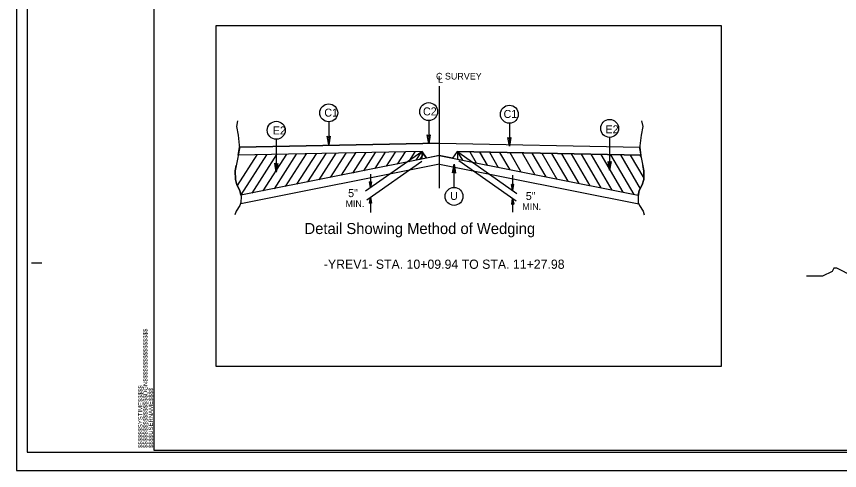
# Model space of a CAD drawing. Extents: x 1818040 to 1825768, y 638918 to 648046.
# Drawn here: x 1820431 to 1821432, y 644030 to 644582 of the extents above; entities that cross this region are included whole.
import ezdxf

# ---------------------------------------------------------------- set-up
doc = ezdxf.new("R2010")
doc.units = 0
for name, color, linetype in [('Old_Level_1', 7, 'Continuous'), ('Sheet Plot Border Inside CELL', 7, 'Continuous'), ('Sheet Plot Border Outside CELL', 7, 'Continuous'), ('Sheet Typical CELL', 7, 'Continuous'), ('Typical Detail Wedge2 CELL', 7, 'Continuous'), ('Typical ID Circle CELL', 7, 'Continuous'), ('Typical Slope Point Local CELL', 7, 'Continuous'), ('Typical Terminator CELL', 7, 'Continuous'), ('Typical Text Centerline CELL', 7, 'Continuous'), ('Typical Text General CELL', 7, 'Continuous'), ('Typical Text Grade Point CELL', 7, 'Continuous'), ('Typical Text ID Circle CELL', 7, 'Continuous')]:
    doc.layers.add(name, color=color, linetype=linetype)

msp = doc.modelspace()

# ---------------------------------------------------------------- linework, layer by layer
at = {"layer": 'Old_Level_1'}
msp.add_lwpolyline([(1820674, 644570.9), (1821287.9, 644570.9), (1821287.9, 644156.3), (1820674, 644156.3)], close=True, dxfattribs=at)
at = {"layer": 'Sheet Plot Border Inside CELL'}
msp.add_lwpolyline([(1822110.4, 645107.2), (1820443.9, 645107.2), (1820443.9, 644052.1), (1822110.4, 644052.1)], close=True, dxfattribs=at)
at = {"layer": 'Sheet Plot Border Outside CELL'}
msp.add_lwpolyline([(1822114.9, 645129.6), (1820430.9, 645129.6), (1820430.9, 644029.6), (1822114.9, 644029.6)], close=True, dxfattribs=at)
at = {"layer": 'Sheet Typical CELL'}
for p, q in [((1820430.9, 645129.6), (1820430.9, 644029.6)), ((1820449.4, 644282.1), (1820461.9, 644282.1)), ((1820597.9, 644054.6), (1820597.9, 644054.6)), ((1820597.9, 644054.6), (1820597.9, 644054.6)), ((1820597.9, 644054.6), (1820597.9, 644054.6)), ((1820597.9, 644054.6), (1820597.9, 644054.6)), ((1820597.9, 644054.6), (1820597.9, 644054.6)), ((1820597.9, 644054.6), (1820597.9, 644054.6)), ((1820430.9, 644029.6), (1822114.9, 644029.6))]:
    msp.add_line(p, q, dxfattribs=at)
msp.add_lwpolyline([(1822097.9, 645104.6), (1820597.9, 645104.6), (1820597.9, 644054.6), (1822097.9, 644054.6)], close=True, dxfattribs=at)
msp.add_lwpolyline([(1820635.4, 644054.6), (1820635.4, 644054.6)], dxfattribs=at)
at = {"layer": 'Typical Detail Wedge2 CELL'}
for p, q in [((1820945.5, 644372.9), (1820945.5, 644497)), ((1820699.8, 644455), (1820698.5, 644447.9)), ((1820945.5, 644372.9), (1820945.5, 644457.7)), ((1820698.5, 644447.9), (1820700.4, 644437.7)), ((1820700.4, 644437.7), (1820702.1, 644421.3)), ((1820945.5, 644427.7), (1820702, 644422.9)), ((1820702, 644422.9), (1820945.5, 644427.7)), ((1820945.5, 644427.7), (1821189, 644422.9)), ((1820945.5, 644427.7), (1821189, 644422.9)), ((1820702.1, 644421.3), (1820699.8, 644408.4)), ((1820700.6, 644413.1), (1820702, 644422.9)), ((1820924.2, 644417.6), (1820700.6, 644413.1)), ((1820924.2, 644417.6), (1820700.6, 644413.1)), ((1820795.3, 644415), (1820771.5, 644377.9)), ((1820807.3, 644415.2), (1820785.1, 644380.6)), ((1820819.3, 644415.5), (1820798.7, 644383.3)), ((1820831.4, 644415.7), (1820812.4, 644386.1)), ((1820843.4, 644415.9), (1820826, 644388.8)), ((1820855.4, 644416.2), (1820839.6, 644391.5)), ((1820867.4, 644416.4), (1820853.2, 644394.2)), ((1820923.9, 644417.4), (1820855.3, 644369.3)), ((1820879.5, 644416.7), (1820866.8, 644397)), ((1820891.5, 644416.9), (1820880.5, 644399.7)), ((1820903.5, 644417.2), (1820894.1, 644402.4)), ((1820915.6, 644417.4), (1820907.7, 644405.1)), ((1820917.2, 644407.2), (1820923.8, 644417.5)), ((1820925.9, 644415), (1820921.3, 644407.9)), ((1820923.8, 644417.5), (1820923.8, 644409)), ((1820929.6, 644409.5), (1820924.2, 644417.6)), ((1820924.2, 644417.3), (1820929.6, 644409.5)), ((1820967.1, 644417.6), (1820961.4, 644409.5)), ((1820967.1, 644417.6), (1820961.4, 644409.5)), ((1820966.7, 644417.4), (1820967, 644417.4)), ((1820967.1, 644417.6), (1821190.4, 644413.1)), ((1821190.4, 644413.1), (1820967.1, 644417.6)), ((1820973.8, 644407.2), (1820967.2, 644417.5)), ((1820967.2, 644417.5), (1820967.2, 644408.1)), ((1820968.9, 644416.3), (1821039.6, 644366.8)), ((1820982.3, 644417.3), (1820990.2, 644403.8)), ((1820994.2, 644417), (1821003.5, 644401.1)), ((1820994.4, 644416.7), (1821003.6, 644401.1)), ((1821006.2, 644416.8), (1821016.9, 644398.4)), ((1821018.6, 644416.5), (1821030.8, 644395.5)), ((1821030.8, 644416.3), (1821044.4, 644392.9)), ((1821046, 644416), (1821061.4, 644389.5)), ((1821057.9, 644415.7), (1821074.8, 644386.8)), ((1821069.9, 644415.5), (1821088.2, 644384.2)), ((1821081.8, 644415.3), (1821101.5, 644381.5)), ((1821093.8, 644415), (1821114.9, 644378.8)), ((1821189, 644422.9), (1821190.4, 644413.1)), ((1820699.8, 644408.4), (1820696.9, 644394.3)), ((1820723.1, 644413.5), (1820699.3, 644376.4)), ((1820735.1, 644413.8), (1820703.8, 644364.8)), ((1820945.9, 644412.8), (1820703.8, 644364.4)), ((1820747.1, 644414), (1820717, 644367)), ((1820759.2, 644414.3), (1820730.6, 644369.7)), ((1820771.2, 644414.5), (1820744.3, 644372.4)), ((1820783.2, 644414.7), (1820757.9, 644375.2)), ((1820924, 644405.6), (1820856.9, 644358.6)), ((1820945.2, 644412.8), (1820929.6, 644409.5)), ((1820945.2, 644412.8), (1821187.2, 644364.4)), ((1820961.4, 644409.5), (1820945.2, 644412.8)), ((1820968.8, 644406.6), (1821038.8, 644357.6)), ((1821105.7, 644414.8), (1821128.3, 644376.1)), ((1821117.7, 644414.6), (1821141.6, 644373.5)), ((1821129.6, 644414.3), (1821155, 644370.8)), ((1821141.6, 644414.1), (1821168.4, 644368.1)), ((1821153.5, 644413.8), (1821181.7, 644365.5)), ((1821165.5, 644413.6), (1821189.5, 644372.4)), ((1821177.4, 644413.4), (1821193.9, 644385.1)), ((1821189.3, 644413.1), (1821190.8, 644410.6)), ((1820945.4, 644402.4), (1820703.8, 644354)), ((1820945.6, 644402.4), (1821187.8, 644353.9)), ((1820696.9, 644394.3), (1820697.2, 644383.7)), ((1820846.6, 644392.9), (1820839, 644391.4)), ((1820861.5, 644390), (1820861.5, 644373.7)), ((1821034.4, 644389.1), (1821034.4, 644370.4)), ((1820697.2, 644383.7), (1820698.9, 644377)), ((1820698.9, 644377), (1820702.8, 644370.3)), ((1820861.5, 644373.7), (1820860.3, 644380.9)), ((1820861.5, 644379.9), (1820860.3, 644380.9)), ((1820861.5, 644373.7), (1820860.4, 644380.7)), ((1820860.6, 644380.6), (1820861.5, 644373.7)), ((1820861.5, 644373.7), (1820860.8, 644380.5)), ((1820861, 644380.3), (1820861.5, 644373.7)), ((1820861.5, 644373.7), (1820861.2, 644380.2)), ((1820861.3, 644380.1), (1820861.5, 644373.7)), ((1820861.5, 644373.7), (1820862.8, 644380.9)), ((1820862.8, 644380.9), (1820861.5, 644379.9)), ((1820862.6, 644380.7), (1820861.5, 644373.7)), ((1820861.5, 644373.7), (1820862.4, 644380.6)), ((1820862.2, 644380.5), (1820861.5, 644373.7)), ((1820861.5, 644373.7), (1820862.1, 644380.3)), ((1820861.9, 644380.2), (1820861.5, 644373.7)), ((1820861.5, 644373.7), (1820861.7, 644380.1)), ((1820861.5, 644379.9), (1820861.5, 644373.7)), ((1821034.4, 644370.4), (1821033.2, 644377.5)), ((1821034.4, 644376.6), (1821033.2, 644377.5)), ((1821034.4, 644370.4), (1821033.4, 644377.4)), ((1821033.5, 644377.3), (1821034.4, 644370.4)), ((1821034.4, 644370.4), (1821033.7, 644377.1)), ((1821033.9, 644377), (1821034.4, 644370.4)), ((1821034.4, 644370.4), (1821034.1, 644376.9)), ((1821034.2, 644376.8), (1821034.4, 644370.4)), ((1821034.4, 644370.4), (1821035.7, 644377.5)), ((1821035.7, 644377.5), (1821034.4, 644376.6)), ((1821035.5, 644377.4), (1821034.4, 644370.4)), ((1821034.4, 644370.4), (1821035.3, 644377.3)), ((1821035.2, 644377.1), (1821034.4, 644370.4)), ((1821034.4, 644370.4), (1821035, 644377)), ((1821034.8, 644376.9), (1821034.4, 644370.4)), ((1821034.4, 644370.4), (1821034.6, 644376.8)), ((1821034.4, 644376.6), (1821034.4, 644370.4)), ((1820702.8, 644370.3), (1820704.1, 644363)), ((1820703.9, 644355.7), (1820702.6, 644352.2)), ((1820704.1, 644363), (1820703.9, 644355.7)), ((1820861.5, 644361.9), (1820860.3, 644354.7)), ((1820860.3, 644354.7), (1820861.5, 644355.6)), ((1820860.4, 644354.8), (1820861.5, 644361.9)), ((1820861.5, 644361.9), (1820860.6, 644355)), ((1820860.8, 644355.1), (1820861.5, 644361.9)), ((1820861.5, 644361.9), (1820861, 644355.2)), ((1820861.2, 644355.4), (1820861.5, 644361.9)), ((1820861.5, 644361.9), (1820861.3, 644355.5)), ((1820861.5, 644361.9), (1820861.5, 644343.5)), ((1820861.5, 644361.9), (1820862.8, 644354.7)), ((1820861.5, 644355.6), (1820861.5, 644361.9)), ((1820861.7, 644355.5), (1820861.5, 644361.9)), ((1820861.5, 644361.9), (1820861.9, 644355.4)), ((1820862.1, 644355.2), (1820861.5, 644361.9)), ((1820861.5, 644361.9), (1820862.2, 644355.1)), ((1820862.4, 644355), (1820861.5, 644361.9)), ((1820861.5, 644361.9), (1820862.6, 644354.8)), ((1820861.5, 644355.6), (1820862.8, 644354.7)), ((1821034.4, 644360.7), (1821033.2, 644353.5)), ((1821033.4, 644353.7), (1821034.4, 644360.7)), ((1821034.4, 644360.7), (1821033.5, 644353.8)), ((1821033.7, 644354), (1821034.4, 644360.7)), ((1821034.4, 644360.7), (1821033.9, 644354.1)), ((1821034.1, 644354.2), (1821034.4, 644360.7)), ((1821034.4, 644360.7), (1821034.2, 644354.3)), ((1821034.4, 644360.7), (1821034.4, 644344)), ((1821034.4, 644360.7), (1821035.7, 644353.5)), ((1821034.4, 644354.5), (1821034.4, 644360.7)), ((1821034.6, 644354.3), (1821034.4, 644360.7)), ((1821034.4, 644360.7), (1821034.8, 644354.2)), ((1821035, 644354.1), (1821034.4, 644360.7)), ((1821034.4, 644360.7), (1821035.2, 644354)), ((1821035.3, 644353.8), (1821034.4, 644360.7)), ((1821034.4, 644360.7), (1821035.5, 644353.7)), ((1820698, 644345.3), (1820696.5, 644340.5)), ((1820702.6, 644352.2), (1820698, 644345.3)), ((1821033.2, 644353.5), (1821034.4, 644354.5)), ((1821034.4, 644354.5), (1821035.7, 644353.5))]:
    msp.add_line(p, q, dxfattribs=at)
for points in [[(1821191.3, 644455), (1821192.6, 644447.9), (1821190.6, 644437.7), (1821188.9, 644421.3), (1821191.3, 644408.4), (1821194.1, 644394.3), (1821193.9, 644383.7), (1821192.1, 644377), (1821188.3, 644370.3), (1821187, 644363), (1821187.2, 644355.7), (1821188.5, 644352.2), (1821193, 644345.3), (1821194.5, 644340.5)], [(1820703.8, 644364.4), (1820702.8, 644370.3), (1820698.9, 644377), (1820697.2, 644383.7), (1820696.9, 644394.3), (1820698.2, 644400.8)], [(1821187.2, 644364.4), (1821188.3, 644370.3), (1821192.1, 644377), (1821193.9, 644383.7), (1821194.1, 644394.3), (1821192.8, 644400.8)]]:
    msp.add_lwpolyline(points, dxfattribs=at)
at = {"layer": 'Typical ID Circle CELL'}
for p, q in [((1820932.3, 644455.3), (1820932.3, 644427.2)), ((1820810.7, 644453.8), (1820810.7, 644425.7)), ((1821030.4, 644452.2), (1821030.4, 644424.1)), ((1820746.9, 644432.7), (1820746.9, 644392.7)), ((1821152.4, 644434.9), (1821152.4, 644394.9)), ((1820963.1, 644374), (1820963.1, 644402.1))]:
    msp.add_line(p, q, dxfattribs=at)
for centre in [(1820810.7, 644464.7), (1820932.3, 644466.2), (1821030.4, 644463), (1821152.4, 644445.8), (1820746.9, 644443.5), (1820963.1, 644363.1)]:
    msp.add_circle(centre, 10.9, dxfattribs=at)
at = {"layer": 'Typical Slope Point Local CELL'}
msp.add_lwpolyline([(1821469.7, 644271.8), (1821454.2, 644269.9), (1821450.3, 644269.9), (1821444.4, 644269.9), (1821440.5, 644269.9), (1821436.7, 644271.8), (1821432.8, 644273.8), (1821428.9, 644275.7), (1821425, 644275.7), (1821423, 644271.8), (1821419.1, 644269.9), (1821415.2, 644267.9), (1821411.4, 644266), (1821407.5, 644266), (1821403.6, 644266), (1821399.7, 644266), (1821395.8, 644266), (1821391.9, 644266)], dxfattribs=at)
at = {"layer": 'Typical Terminator CELL'}
for points in [[(1820812.5, 644436.2), (1820810.7, 644425.7), (1820808.8, 644436.3), (1820810.7, 644434.9)], [(1820812.5, 644436.2), (1820810.7, 644425.7), (1820808.8, 644436.3), (1820810.7, 644434.9)], [(1820934.1, 644437.8), (1820932.3, 644427.2), (1820930.4, 644437.8), (1820932.3, 644436.5)], [(1820934.1, 644437.8), (1820932.3, 644427.2), (1820930.4, 644437.8), (1820932.3, 644436.5)], [(1821032.2, 644434.6), (1821030.4, 644424.1), (1821028.5, 644434.7), (1821030.4, 644433.3)], [(1821154.2, 644405.5), (1821152.4, 644394.9), (1821150.5, 644405.5), (1821152.4, 644404.2)], [(1820748.8, 644403.2), (1820746.9, 644392.7), (1820745.1, 644403.3), (1820746.9, 644402)], [(1820748.8, 644403.2), (1820746.9, 644392.7), (1820745.1, 644403.3), (1820746.9, 644402)], [(1820961.3, 644391.6), (1820963.1, 644402.1), (1820965, 644391.5), (1820963.1, 644392.9)], [(1820961.3, 644391.6), (1820963.1, 644402.1), (1820965, 644391.5), (1820963.1, 644392.9)]]:
    msp.add_lwpolyline(points, close=True, dxfattribs=at)

# ---------------------------------------------------------------- texts
at = {"layer": 'Sheet Typical CELL'}
for s, p in [('$$$$$$$$$$$$$$$$DGN$$$$$$$$$$$$$$$$', (1820590.3, 644057)), ('$$$$$$SYSTIME$$$$$', (1820584.2, 644057)), ('$$$$USERNAME$$$$', (1820596.9, 644057))]:
    msp.add_text(s, height=5.25, rotation=90, dxfattribs=at).set_placement(p)
at = {"layer": 'Typical Detail Wedge2 CELL'}
for s, height, p in [('5"', 9.73, (1820834.3, 644362.2)), ('5"', 9.73, (1821050.4, 644358.7)), ('MIN.', 8.13, (1820831.1, 644350.2)), ('MIN.', 8.13, (1821046.1, 644346.7))]:
    msp.add_text(s, height=height, dxfattribs=at).set_placement(p)
at = {"layer": 'Typical Text Centerline CELL'}
for s, p in [('C SURVEY ', (1820941.2, 644505.2)), ('L', (1820943.6, 644501.4))]:
    msp.add_text(s, height=8.13, dxfattribs=at).set_placement(p)
at = {"layer": 'Typical Text General CELL'}
msp.add_text('Detail Showing Method of Wedging', height=13.428, dxfattribs=at).set_placement((1820781.3, 644317.3))
at = {"layer": 'Typical Text Grade Point CELL'}
msp.add_text('-YREV1- STA. 10+09.94 TO STA. 11+27.98', height=11.19, dxfattribs=at).set_placement((1820804.8, 644275))
at = {"layer": 'Typical Text ID Circle CELL'}
for s, p in [('C1', (1820805.4, 644460.1)), ('C2', (1820925.4, 644461.6)), ('C1', (1821023.4, 644458.5)), ('E2', (1820742.7, 644438.4)), ('E2', (1821147.3, 644439.8)), ('U', (1820958.4, 644358.8))]:
    msp.add_text(s, height=9.73, dxfattribs=at).set_placement(p)

doc.saveas('drawing.dxf')
